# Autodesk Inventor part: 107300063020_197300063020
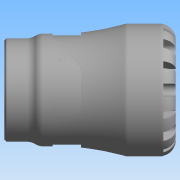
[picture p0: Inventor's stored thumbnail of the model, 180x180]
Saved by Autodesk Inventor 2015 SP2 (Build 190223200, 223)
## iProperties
Created: 2016-12
Part Number: 107300063020_197300063020
Material: Generic
Description: PLASSON FEMALE INTEGRAL BRASS THREAD 63X2" SERIES 1
Document SubType Name: Modeling
Designer: KIM
Density: 1 g/cm^3
Appearance: Default
Author: KIM
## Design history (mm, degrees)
derived "1073.ipt"
feature "Solid1::1073.ipt"
tag "TaggingFeature1"
body "Solid1"
other parameters: "d0" = 133, "d1" = 38.64, "d2" = 63, "d3" = 78.75, "d4" = 103, "d6" = 92, "d8" = 87.55, "d13" = 9.7, "d14" = 9.7, "d15" = 0, "d17" = 360 deg, "d19" = 8 deg, "d20" = 1.26, "d21" = 1.26, "d22" = 8 deg, "d24" = 0, "d26" = 360 deg, "d32" = 10.3, "d33" = 10.3, "d39" = 1.69968, "d42" = 56.656, "d43" = 80.34, "d46" = 5.25, "d47" = 26, "d48" = 53.8232, "d50" = 4.95, "d51" = 1.03, "d54" = 22.05, "d55" = 13.86, "d57" = 19.012, "d58" = 0, "d68" = 360 deg, "d72" = 1.26, "d74" = 0, "d76" = 18.7425, "d_" = 63, "E_" = 103, "H_" = 133, "l_" = 92, "G_" = 56.656, "l_2" = 26, "d9" = 12.125, "d11" = 103, "d12" = 78.75, "d49" = 15
